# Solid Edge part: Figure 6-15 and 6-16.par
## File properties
Author: TIET
Template: iso metric part.par
Last saved by: CADCIM
Revision: 3
Application: Solid Edge
Accuracy: 0.990
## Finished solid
Body 1: solid body, 10 faces, 24 edges, 16 vertices.
  Faces by surface: plane 6, cylinder 4
  Edges by curve: line 16, circle 8
Bounding box of the edges (mm): 143.197 x 98.531 x 20.822, from (-71.5983, -49.2655, 0) to (71.5983, 49.2655, 20.8222).
Cylindrical faces by radius (mm): R15 x4
Planar faces by outward normal: +x 1, +y 1, +z 1, -x 1, -y 1, -z 1
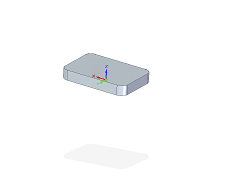
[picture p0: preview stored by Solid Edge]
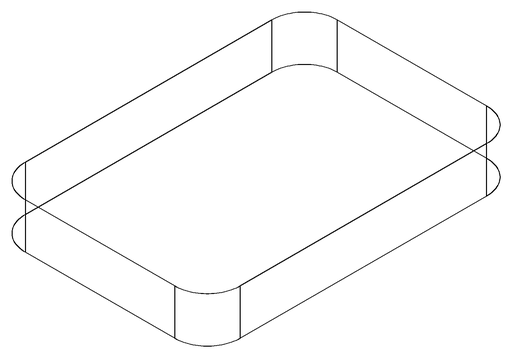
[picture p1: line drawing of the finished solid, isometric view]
